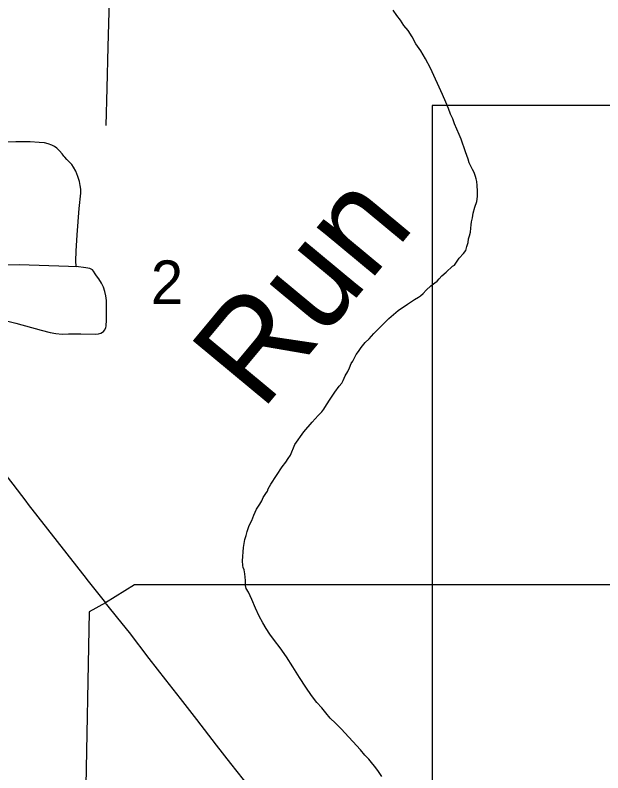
# Model space of a CAD drawing. Extents: x 0 to 34, y 0 to 22.
# Drawn here: x 26.2909 to 26.5735, y 17.8568 to 18.2214 of the extents above; entities that cross this region are included whole.
import ezdxf

# ---------------------------------------------------------------- set-up
doc = ezdxf.new("R2010")
doc.units = 0
for name, color, linetype in [('GM_X_City_Street', 7, 'Continuous'), ('GM_X_Corporation', 7, 'Continuous'), ('GM_X_County_Road', 7, 'Continuous'), ('GM_X_Minor_River', 7, 'Continuous'), ('GM_X_Minor_River_Text', 7, 'Continuous'), ('GM_X_Section_Text', 7, 'Continuous'), ('GM_X_State_Route', 7, 'Continuous'), ('SH_Text', 7, 'Continuous')]:
    doc.layers.add(name, color=color, linetype=linetype)

msp = doc.modelspace()

# ---------------------------------------------------------------- linework, layer by layer
at = {"layer": 'GM_X_City_Street'}
msp.add_lwpolyline([(26.33462, 18.16825), (26.33508, 18.18619), (26.33559, 18.20615), (26.33634, 18.23442)], dxfattribs=at)
at = {"layer": 'GM_X_Corporation'}
msp.add_lwpolyline([(26.5779, 17.94735), (26.39459, 17.94724), (26.39141, 17.94725), (26.34828, 17.94731), (26.33429, 17.93864), (26.32645, 17.93423), (26.32468, 17.84219)], dxfattribs=at)
at = {"layer": 'GM_X_County_Road'}
for points in [[(26.33456, 18.07169), (26.33469, 18.0723), (26.33483, 18.07416), (26.33483, 18.08069), (26.33473, 18.0841), (26.33449, 18.08626), (26.33401, 18.08838), (26.3333, 18.09044), (26.33236, 18.0924), (26.33107, 18.09453), (26.32995, 18.09601), (26.32938, 18.09695), (26.32859, 18.09814), (26.32801, 18.09878), (26.32737, 18.09921), (26.32671, 18.09948), (26.32487, 18.0998), (26.32017, 18.10044), (26.32011, 18.10325), (26.32026, 18.1079), (26.32061, 18.11566), (26.32167, 18.12836), (26.32241, 18.13578), (26.32242, 18.13764), (26.32221, 18.13949), (26.32181, 18.14131), (26.32105, 18.14368), (26.31999, 18.14627), (26.31898, 18.14819), (26.31809, 18.14946), (26.31704, 18.15061), (26.31569, 18.1519), (26.31469, 18.15305), (26.31432, 18.1535), (26.31396, 18.15398), (26.31342, 18.1547), (26.31223, 18.15613), (26.31087, 18.15741), (26.30986, 18.15812), (26.30848, 18.15883), (26.30672, 18.15946), (26.30491, 18.15988), (26.30244, 18.16017), (26.2981, 18.16037), (26.29126, 18.16039), (26.27666, 18.16021)], [(26.27706, 18.10117), (26.29288, 18.10135), (26.31645, 18.10057), (26.32017, 18.10044)], [(26.28604, 18.07453), (26.29116, 18.07322), (26.30342, 18.06974), (26.30764, 18.0687), (26.3104, 18.06822), (26.31349, 18.06796), (26.31659, 18.06797), (26.3225, 18.06808), (26.32933, 18.06789), (26.33087, 18.06805), (26.33206, 18.0684), (26.33291, 18.06881), (26.33339, 18.06919), (26.33393, 18.06994), (26.33442, 18.07109), (26.33456, 18.07169)]]:
    msp.add_lwpolyline(points, dxfattribs=at)
at = {"layer": 'GM_X_Minor_River'}
for points in [[(26.46338, 18.06828), (26.46652, 18.0714), (26.47064, 18.07544), (26.47513, 18.07927), (26.4796, 18.08234), (26.4829, 18.08451), (26.48484, 18.08577), (26.4858, 18.08631), (26.48717, 18.0874), (26.48855, 18.08906), (26.49071, 18.09108), (26.49266, 18.09253), (26.49382, 18.09344), (26.49481, 18.09454), (26.496, 18.09602), (26.49814, 18.09766), (26.50128, 18.10059), (26.50224, 18.10113), (26.50345, 18.10299), (26.50445, 18.10447), (26.50642, 18.10668), (26.50761, 18.10816), (26.50805, 18.11005), (26.50869, 18.11193), (26.50894, 18.11382), (26.50937, 18.11514), (26.50981, 18.11703), (26.51007, 18.11892), (26.51012, 18.12044), (26.51037, 18.12195), (26.51081, 18.12384), (26.51108, 18.12612), (26.51194, 18.12894), (26.51298, 18.13176), (26.51302, 18.1329), (26.51326, 18.13422), (26.51316, 18.1367), (26.51306, 18.13936), (26.51294, 18.14127), (26.51261, 18.14261), (26.51227, 18.14377), (26.51158, 18.1457), (26.51087, 18.14705), (26.50998, 18.1488), (26.50928, 18.15035), (26.50877, 18.15208), (26.50738, 18.15555), (26.50532, 18.16172), (26.50445, 18.16403), (26.50216, 18.16906), (26.5013, 18.17157), (26.50024, 18.1737), (26.4992, 18.1764), (26.49798, 18.17949), (26.4964, 18.18316), (26.4906, 18.19593), (26.48829, 18.20039), (26.48597, 18.20428), (26.48362, 18.2076), (26.48184, 18.2109), (26.47986, 18.21401), (26.47786, 18.21637), (26.47624, 18.2189), (26.47443, 18.22125), (26.47263, 18.22379)], [(26.46727, 17.85501), (26.46528, 17.85794), (26.46365, 17.86009), (26.4622, 17.86186), (26.46093, 17.86342), (26.4591, 17.86539), (26.45692, 17.86795), (26.44761, 17.87799), (26.44486, 17.88075), (26.44229, 17.88313), (26.44029, 17.88567), (26.43829, 17.88803), (26.43592, 17.89059), (26.43339, 17.8941), (26.43068, 17.89801), (26.42763, 17.90268), (26.42439, 17.90775), (26.42134, 17.91261), (26.41827, 17.91691), (26.41555, 17.92044), (26.41339, 17.92356), (26.41159, 17.92629), (26.40998, 17.92901), (26.40819, 17.93212), (26.40643, 17.93599), (26.40469, 17.94024), (26.4031, 17.94372), (26.40203, 17.94547), (26.4017, 17.94701), (26.40159, 17.94929), (26.40133, 17.95254), (26.40102, 17.95445), (26.40049, 17.95561), (26.40033, 17.95657), (26.40022, 17.95886), (26.40064, 17.96531), (26.40134, 17.96909), (26.40197, 17.97097), (26.40242, 17.97286), (26.40347, 17.97586), (26.4047, 17.97829), (26.40573, 17.98073), (26.40697, 17.98373), (26.40857, 17.98615), (26.40957, 17.98763), (26.4102, 17.98932), (26.4114, 17.99118), (26.4122, 17.9923), (26.41262, 17.99342), (26.41383, 17.99566), (26.41924, 18.00403), (26.42103, 18.00625), (26.42223, 18.00811), (26.42323, 18.00959), (26.42531, 18.01485), (26.42969, 18.02097), (26.43364, 18.02558), (26.4366, 18.02871), (26.43837, 18.03055), (26.43936, 18.03185), (26.44057, 18.0339), (26.44237, 18.03669), (26.44457, 18.04003), (26.44676, 18.04281), (26.44794, 18.04429), (26.44856, 18.0456), (26.44959, 18.04784), (26.45079, 18.04989), (26.45162, 18.05176), (26.45245, 18.05383), (26.45325, 18.05494), (26.45386, 18.05625), (26.45487, 18.05812), (26.45606, 18.0596), (26.45726, 18.06146), (26.45924, 18.06386), (26.4612, 18.06569), (26.46338, 18.06828)]]:
    msp.add_lwpolyline(points, dxfattribs=at)
at = {"layer": 'GM_X_State_Route'}
msp.add_line((26.33455, 17.93819), (26.33486, 17.93781), dxfattribs=at)
for points in [[(26.21483, 18.09114), (26.22377, 18.07973), (26.23766, 18.0622), (26.25102, 18.04545), (26.26361, 18.02926), (26.27151, 18.01889), (26.27789, 18.01079), (26.28362, 18.00353), (26.28459, 18.00227), (26.28969, 17.99566), (26.29593, 17.98753), (26.29715, 17.98596)], [(26.29715, 17.98596), (26.32498, 17.95032), (26.3253, 17.94992)], [(26.3253, 17.94992), (26.33424, 17.93857), (26.33455, 17.93819)], [(26.33486, 17.93781), (26.3401, 17.9313), (26.34573, 17.92426), (26.35517, 17.9119), (26.36315, 17.90158), (26.37022, 17.89252), (26.37801, 17.88243), (26.38752, 17.87015), (26.39443, 17.86136), (26.40058, 17.85354), (26.40511, 17.84761), (26.41116, 17.83931), (26.4149, 17.83395), (26.41763, 17.82978), (26.42076, 17.82476), (26.42515, 17.81723), (26.42957, 17.80901), (26.43489, 17.79881), (26.44163, 17.7855), (26.44947, 17.77009)]]:
    msp.add_lwpolyline(points, dxfattribs=at)
at = {"layer": 'SH_Text'}
msp.add_lwpolyline([(28.42481, 18.17793), (26.49145, 18.17793), (26.49145, 17.77484), (28.42481, 17.77484), (28.42481, 17.87561), (28.73475, 18.11868), (28.42481, 17.97638)], close=True, dxfattribs=at)

# ---------------------------------------------------------------- texts
at = {"layer": 'GM_X_Minor_River_Text'}
msp.add_text('Run', height=0.047335, rotation=50.2831, dxfattribs=at).set_placement((26.4094, 18.03046))
at = {"layer": 'GM_X_Section_Text'}
msp.add_text('2', height=0.02093, rotation=0, dxfattribs=at).set_placement((26.35612, 18.08243))

doc.saveas('drawing.dxf')
